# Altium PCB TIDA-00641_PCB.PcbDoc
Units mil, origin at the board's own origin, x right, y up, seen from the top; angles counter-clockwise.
Board outline 1800 x 1950 mil, 2 copper layers (Top Layer, Bottom Layer), stack 62 mil thick; 47 components, 47 nets, 167 pads, 110 vias.
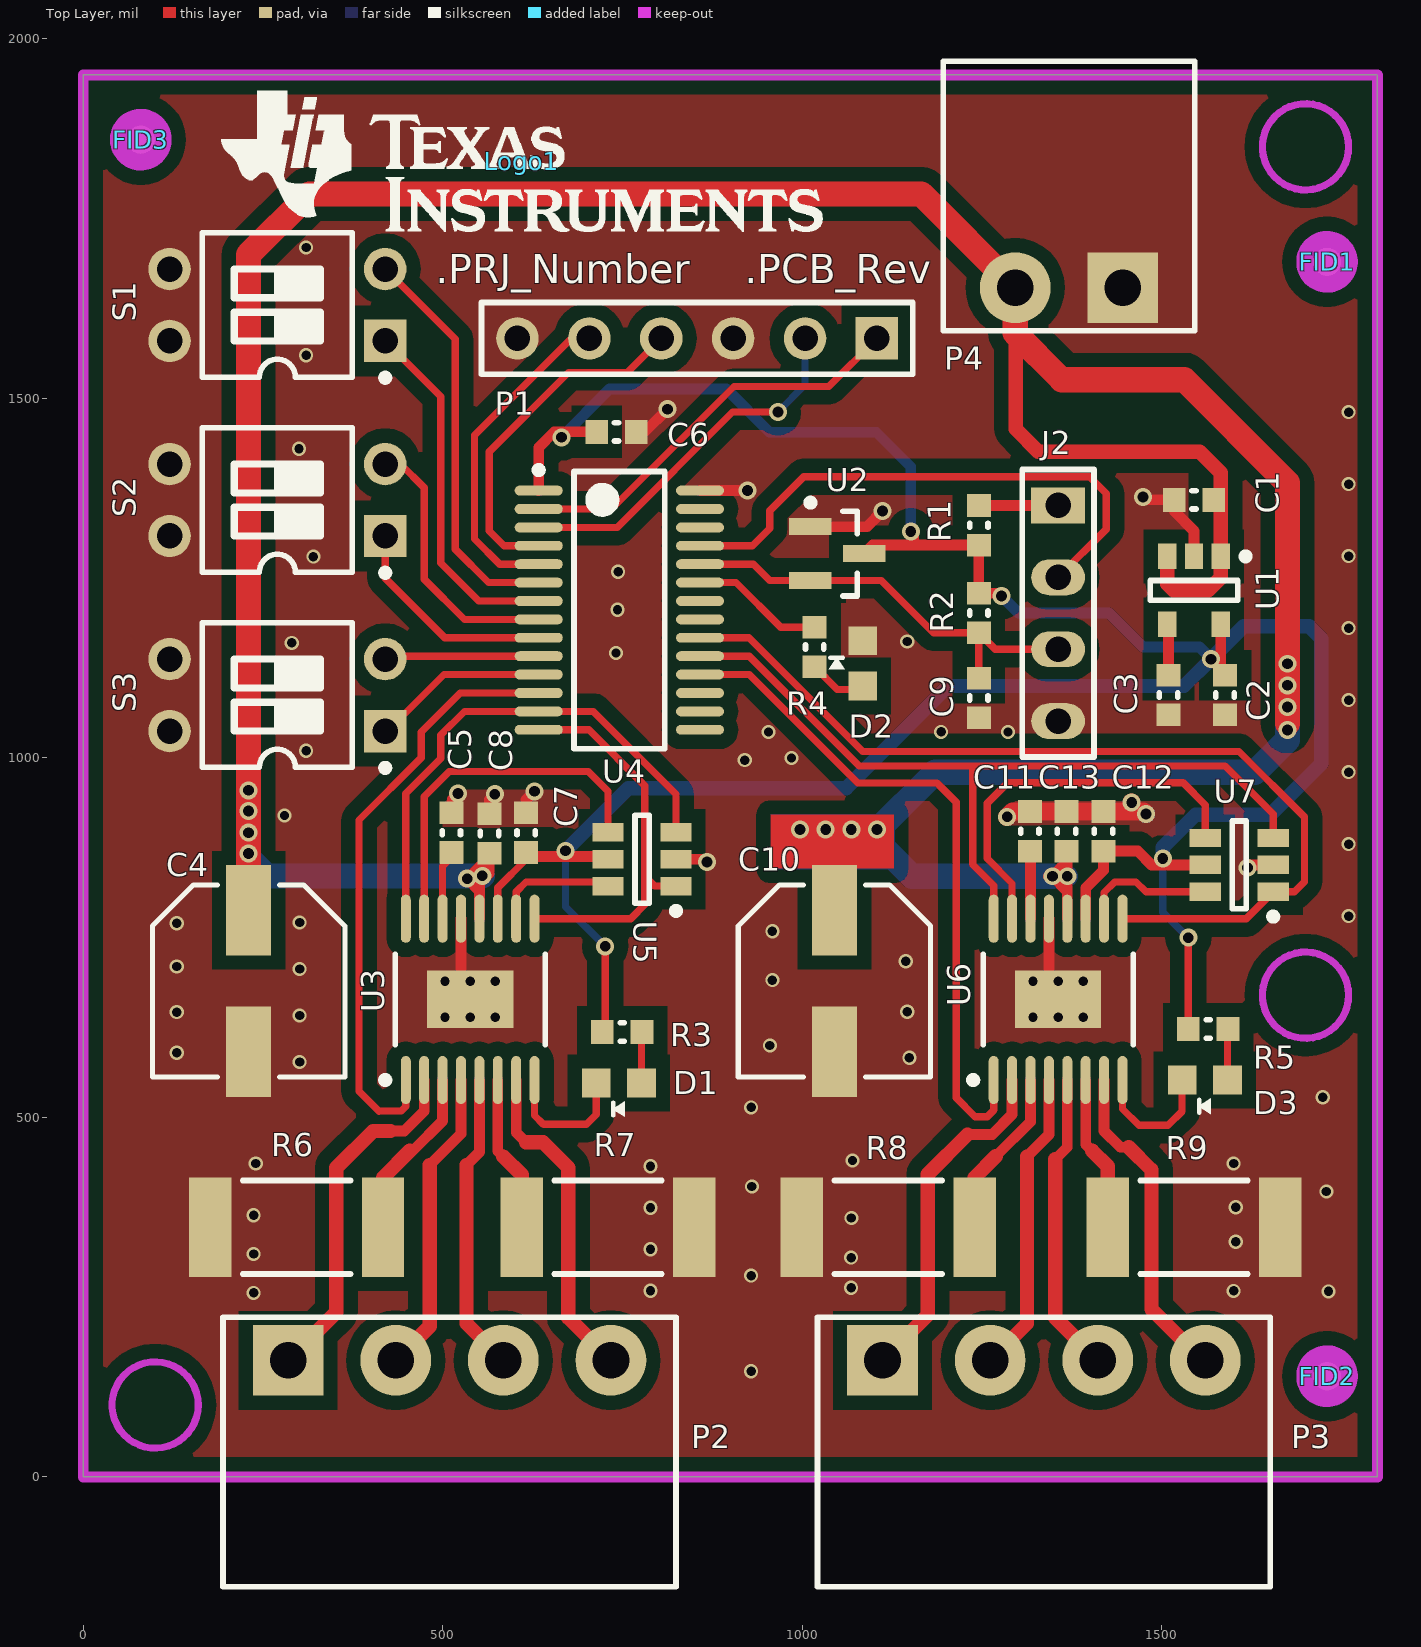
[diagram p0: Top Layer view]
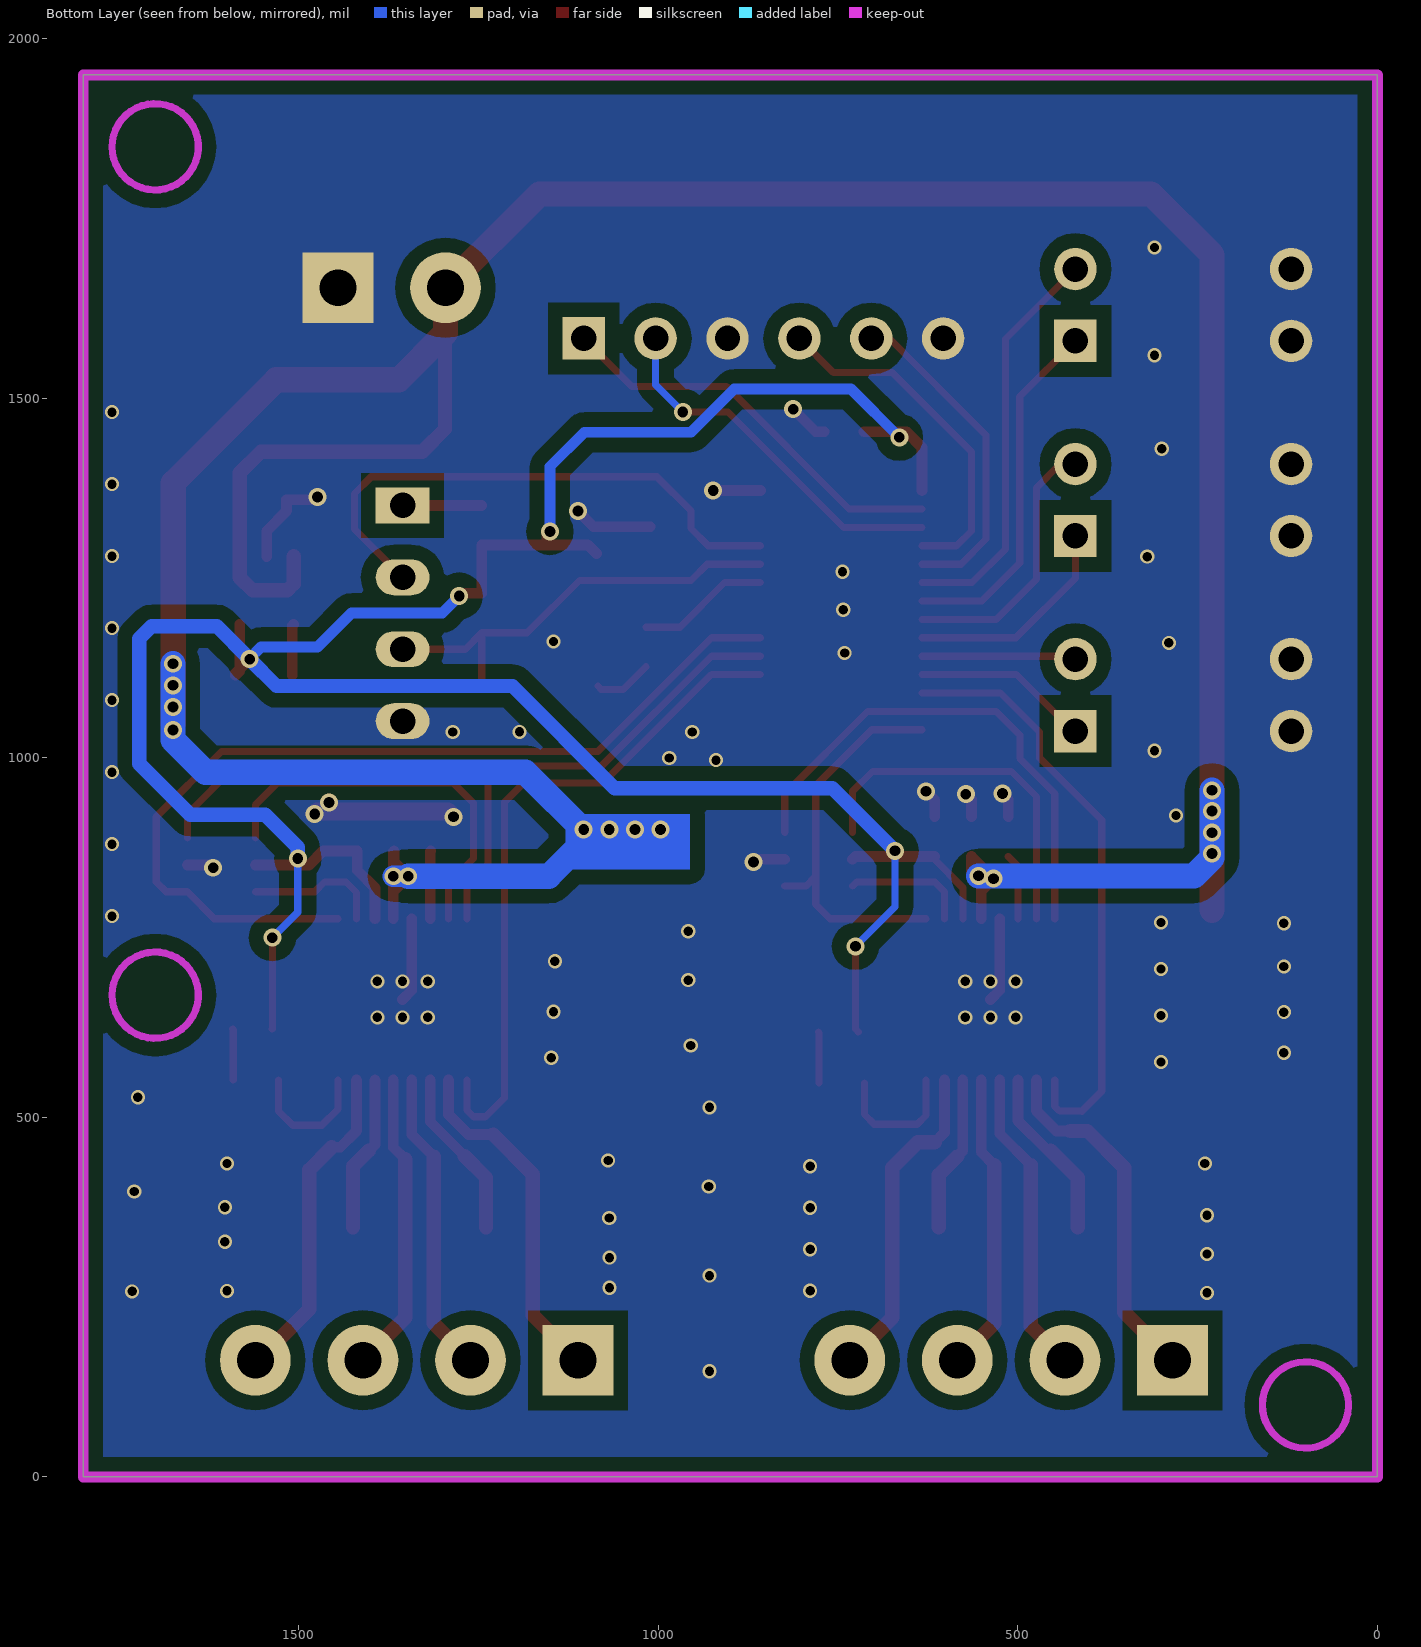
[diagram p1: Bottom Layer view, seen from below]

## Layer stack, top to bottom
Top Solder: solder mask 0.4, Solder Resist, Dk 3.5
Top Layer: signal copper 1.4
Dielectric1: core 59.2, FR-4, Dk 4.8
Bottom Layer: signal copper 1.4
Bottom Solder: solder mask 0.4, Solder Resist, Dk 3.5

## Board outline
0,0 1800,0 1800,1950 0,1950

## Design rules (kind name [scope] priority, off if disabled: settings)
AcuteAngle [All] p1: minimum=4.50000000000000E+0001 checktracksonly=FALSE
AssemblyTestPointUsage [All] p1: valid=2
Clearance Clearance_Keepouts [((IsTrack Or IsArc) And Not InPoly) And IsFree and IsKeepOut vs ((IsTrack Or IsArc) And Not InPoly) And IsFree and IsKeepOut] p1: gap=0
Clearance Clearance_BoardEdge_MountingHoles [OnCopper and InComponentClass('Mounting Holes') vs IsKeepOut] p2: gap=40
Clearance Clearance_BoardEdge_Poly [OnCopper and InPoly vs IsKeepOut] p3: gap=20
Clearance Clearance_BoardEdge [OnCopper and Not InComponentClass('Logo') and not InComponentClass('FiducialMark') and not InRegion(1000,500,4000,800) and Not IsKeepout vs IsKeepOut] p4: gap=20
Clearance Clearance_Poly [InPolygon] p5: gap=20
Clearance [All] p6: gap=8
ComponentClearance ComponentClearance_MountingHoles_FiducialMarks [InComponentClass('Mounting Holes') vs InComponentClass('FiducialMark')] p1 off: gap=50 collisioncheckmode=3 verticalgap=10 showdistances=FALSE
ComponentClearance ComponentClearance_Shunt [InComponentClass('Header') vs InComponentClass('Shunt')] p2 off: gap=0 collisioncheckmode=3 verticalgap=0 showdistances=FALSE
ComponentClearance ComponentClearance_Logo [InComponentClass('Logo')] p3 off: gap=50 collisioncheckmode=3 verticalgap=10 showdistances=FALSE
ComponentClearance ComponentClearance_ScrewToNut [(HasFootprint('NY PMS 440 0025 PH')) vs (HasFootprint('Keystone_1902C'))] p4 off: gap=5 collisioncheckmode=3 verticalgap=10 showdistances=FALSE
ComponentClearance ComponentClearance_MountingHoles [InComponentClass('Mounting Holes')] p5 off: gap=250 collisioncheckmode=3 verticalgap=100000 showdistances=FALSE
ComponentClearance ComponentClearance_SmallPassives [HasFootprint('0201*') or HasFootprint('0402*') or HasFootprint('0508') or HasFootprint('0603*') or HasFootprint('0612') or HasFootprint('0805*') or HasFootprint('0815*') or HasFootprint('0830*') or HasFootprint('1206*') or HasFootprint('1210*') or HasFootprint('1808*') or HasFootprint('1812*') or HasFootprint('1825*') or HasFootprint('2010*') or HasFootprint('2220*') or HasFootprint('2225*') or HasFootprint('2512*') or HasFootprint('2728*') or HasFootprint('3518*') vs HasFootprint('0201*') or HasFootprint('0402*') or HasFootprint('0508') or HasFootprint('0603*') or HasFootprint('0612') or HasFootprint('0805*') or HasFootprint('0815*') or HasFootprint('0830*') or HasFootprint('1206*') or HasFootprint('1210*') or HasFootprint('1808*') or HasFootprint('1812*') or HasFootprint('1825*') or HasFootprint('2010*') or HasFootprint('2220*') or HasFootprint('2225*') or HasFootprint('2512*') or HasFootprint('2728*') or HasFootprint('3518*')] p6 off: gap=20 collisioncheckmode=3 verticalgap=10 showdistances=FALSE
ComponentClearance ComponentClearance_THtoSMT [IsThruComponent vs IsSMTComponent] p7 off: gap=100 collisioncheckmode=3 verticalgap=30 showdistances=FALSE
ComponentClearance ComponentClearance_THtoTH [IsThruComponent vs IsThruComponent] p8 off: gap=118.11 collisioncheckmode=3 verticalgap=30 showdistances=FALSE
ComponentClearance [All] p9 off: gap=0 collisioncheckmode=3 verticalgap=10 showdistances=FALSE
DiffPairsRouting [All] p1: maxlimit=100 minlimit=10 mostfreqgap=10 toplayer_minwidth=15 toplayer_maxwidth=15 toplayer_prefwidth=15 bottomlayer_minwidth=15 bottomlayer_maxwidth=15 bottomlayer_prefwidth=15 maxuncoupledlength=1000
FabricationTestPointUsage TestPointUsage [All] p1: valid=2 allowmultiple=FALSE
FabricationTestpoint Testpoint [All] p1: side=3 testpointundercomponent=TRUE minsize=40 maxsize=100 preferedsize=60 minholesize=0 maxholesize=40 preferedholesize=32 testpointgrid=1 allowsidetop=TRUE allowsidebottom=TRUE usegrid=TRUE gridtolerance=0.01
FanoutControl Fanout_LCC [IsLCC] p1: bgadir=Out bgaviamode=Centered fanoutstyle=Auto fanoutdirection=Alternating viagrid=1 // Fanout_LCC (Default Rule)
FanoutControl Fanout_BGA [IsBGA] p2: bgadir=Out bgaviamode=Centered fanoutstyle=Auto fanoutdirection=Alternating viagrid=1 // Fanout_BGA (Default Rule)
FanoutControl Fanout_Default [All] p4: bgadir=Out bgaviamode=Centered fanoutstyle=Auto fanoutdirection=Alternating viagrid=1 // Fanout_Default (Default Rule)
FanoutControl Fanout_Small [(CompPinCount < 5)] p5: bgadir=Out bgaviamode=Centered fanoutstyle=Auto fanoutdirection=OutThenIn viagrid=1 // Fanout_Small (Default Rule)
HoleSize [All] p1: absolutevalues=TRUE maxlimit=251 minlimit=8 maxpercent=80.000 minpercent=20.000
MinimumAnnularRing MinimumAnnularRing_ThermalPadVias [IsVia and InAnyComponent] p1: minimumring=5.91
MinimumAnnularRing [All] p2: minimumring=9
PlaneConnect [All] p1: planeconnectstyle=Relief reliefexpansion=10 reliefentries=4 reliefconductorwidth=10 reliefairgap=10
PolygonConnect [All] p1: connectstyle=Direct reliefconductorwidth=10 reliefentries=4 polygonreliefangle="90 Angle" airgapwidth=10
RoutingVias ThermalPadVias [IsVia and InAnyComponent] p1 off: holewidth=7.87 width=19.68 viastyle="Through Hole" minholewidth=7.87 minwidth=19.68 maxholewidth=12.99 maxwidth=23.62
RoutingVias [All] p2 off: holewidth=16 width=34 viastyle="Through Hole" minholewidth=7.87 minwidth=26 maxholewidth=40 maxwidth=65
SilkToBoardRegionClearance [Not ((IsComment or IsDesignator) And (Hide <> 'False')) and not InRegion(1000,500,4000,800)] p1:
SilkToSilkClearance SilkToSilkClearance_Pb-FreeLogo [(HasFootprint('Pb-Free_Overlay_Medium') OR HasFootprint('Pb-Free_Overlay_Small')) vs (HasFootprint('Pb-Free_Overlay_Medium') OR HasFootprint('Pb-Free_Overlay_Small'))] p1: silktosilkclearance=0
SilkToSilkClearance [All] p2: silktosilkclearance=4
SolderMaskExpansion [All] p1: expansion=1.97
UnpouredPolygon [All] p1: allowunpoured=FALSE
Width [All] p1: maxlimit=100 minlimit=6 preferedwidth=10 checkconnectedcopper=TRUE
16 further rules are at their usual default settings.

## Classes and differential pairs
component class Logo: Logo1
component class TIDA-00641_TID_Hardware: FID1 FID2 FID3 Logo1 ZZ2 ZZ3 ZZ4
component class FiducialMark: FID1 FID2 FID3
component class AssemblyNote: ZZ2 ZZ3 ZZ4
component class Header: J2
component class TIDA-00641_BlankSheet: C1 C2 C3 C4 C5 C6 C7 C8 C9 C10 C11 C12 C13 D1 D2 D3 J2 P1 P2 P3 P4 R1 R2 R3 R4 R5 R6 R7 R8 R9 S1 S2 S3 U1 U2 U3 U4 U5 U6 U7

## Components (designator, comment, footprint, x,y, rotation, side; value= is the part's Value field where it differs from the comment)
C1 "C0603C105K4PACTU" 0603L 1544.88,1359.06 r180 top
C2 "C0603C225K8PACTU" 0603L 1588.19,1087.4 r90 top
C3 "C0603C103J5RACTU" 0603L 1509.45,1087.4 r270 top
C4 "EEE-FK1E470P" SM_RADIAL_D 229.92,689.76 r270 top
C5 "C0603C225M8PACTU" 0603L 512,896 r90 top
C6 "C0603C104K4RACTU" 0603L 741.73,1453.54 r180 top
C7 "06033C104KAT2A" 0603L 616,896 r270 top
C8 "06033C104KAT2A" 0603L 565,895 r270 top
C9 "C0603C102K5RACTU" 0603L 1245.67,1083.46 r90 top
C10 "EEE-FK1E470P" SM_RADIAL_D 1044.88,689.76 r270 top
C11 "C0603C225K8PACTU" 0603L 1316.54,897.93 r90 top
C12 "06033C104KAT2A" 0603L 1418.9,897.93 r270 top
C13 "06033C104KAT2A" 0603L 1367.72,897.93 r270 top
D1 "LTST-C190KRKT" LED603RED 745.67,548.03 r0 top
D2 "LTST-C190GKT" LED603GRN 1084.25,1130.71 r270 top
D3 "LTST-C190KRKT" LED603RED 1560.63,551.97 r0 top
FID1 "Fiducial" Fiducial10-20 1730,1690 r0 top
FID2 "Fiducial" Fiducial10-20 1730,140 r0 top
FID3 "Fiducial" Fiducial10-20 80,1860 r0 top
J2 "TSW-104-07-G-S" HDR1X4 1355.91,1351.18 r270 top
Logo1 "Texas Instruments" TI_Stacked_Overlay_Small 610,1830 r0 top
P1 "Header 6" HDR1X6 1103.94,1583.46 r180 top
P2 "Header 4" J4-3.81 509.45,162.2 r0 top
P3 "Header 4" J4-3.81 1336.22,162.2 r0 top
P4 "Header 2" j2-3.81 1371,1654 r180 top
R1 "ERJ-3GEY0R00V" 0603L 1245.67,1323.62 r90 top
R2 "CRCW060347K0JNEA" 0603L 1245.67,1201.57 r270 top
R3 "RC0603FR-07390RL" 0603L 749.61,618.9 r180 top
R4 "RC0603FR-07390RL" 0603L 1017.32,1154.33 r90 top
R5 "RC0603FR-07390RL" 0603L 1564.57,622.83 r180 top
R6 "CSRN2512FKR250" 2512M 296.85,347.24 r0 top
R7 "CSRN2512FKR250" 2512M 729.92,347.24 r180 top
R8 "CSRN2512FKR250" 2512M 1119.68,347.24 r0 top
R9 "CSRN2512FKR250" 2512M 1544.88,347.24 r180 top
S1 "SW DIP-2" DIP-4 270,1630 r180 top
S2 "SW DIP-2" DIP-4 270,1358.7 r180 top
S3 "SW DIP-2" DIP-4 270,1087.4 r180 top
U1 "LP2985-33DBVT" MF05A_L 1544.88,1233.07 r270 top
U2 "TLV803S" SOT-23 1048.82,1284.25 r0 top
U3 "DRV8848" PW0016S 538.19,664.17 r90 top
U4 "MSP430G2553IPW28" PW0028A_N 745.67,1205.51 r0 top
U5 "SN74LVC2G14" DBV0006A_N 777.17,859.06 r180 top
U6 "DRV8848" PW0016S 1355.91,664.17 r90 top
U7 "SN74LVC2G14" DBV0006A_N 1607.87,851.18 r180 top
ZZ2 "These assemblies are ESD sensitive, ESD precautions shall be observed." AssemblyNote 185,3829.11 r0 top
ZZ3 "These assemblies must be clean and free from flux and all contaminants. Use of no clean flux is not acceptable." AssemblyNote 185,3740.56 r0 top
ZZ4 "These assemblies must comply with workmanship standards IPC-A-610 Class 2, unless otherwise specified." AssemblyNote 185,3652 r0 top

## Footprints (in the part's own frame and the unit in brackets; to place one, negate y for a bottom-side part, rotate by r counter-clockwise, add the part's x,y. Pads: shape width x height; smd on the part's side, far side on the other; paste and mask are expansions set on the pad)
0603L [mm] "0603 from SM-752 data"
  rect 0.8x0.85 smd: 1(-0.7,0) 2(0.7,0)
  silkscreen extent -0.07,-0.33 0.07,0.33, body extent -0.87,-0.47 0.87,0.47, height 0.85
2512M [mm] "Chip Resistor, Body 6.3x3.2mm, IPC Low Density"
  rect 1.5x3.5 smd: 1(-3.05,0) 2(3.05,0)
  silkscreen extent -1.9,-1.65 1.9,1.65, body extent -3.22,-1.67 3.22,1.67, height 0.71
AssemblyNote [mil] "Assembly Note"
DBV0006A_N [mm] "SOT23, 6-Leads, Body 2.9x1.6mm, Pitch 0.95mm, Lead Span 2.8mm, IPC Medium Density"
  rect 1.1x0.65 smd: 1(-1.2,0.95) 2(-1.2,0) 3(-1.2,-0.95) 4(1.2,-0.95) 5(1.2,0) 6(1.2,0.95)
  silkscreen extent -1.33,-1.55 0.25,1.95, body extent -0.87,-1.52 0.87,1.53, height 1.45
DIP-4 [mm] "DIP; 4 Leads; Row Spacing 7.62 mm; Pitch 2.54 mm"
  rect 1.5x1.5 hole 0.9: 1(-3.81,1.27)
  round 1.5 hole 0.9: 2(-3.81,-1.27) 3(3.81,-1.27) 4(3.81,1.27)
  silkscreen extent -3.94,-2.55 2.65,2.69, body extent -3.15,-2.5 3.15,2.5, height 5.6
Fiducial10-20 [mm]
  round 1 smd mask+0.5: 1(0,0)
  Top Layer keep-out circle w1.178: c0,0 r0.5
HDR1X4 [mm] "Connector; Header; 4 Position"
  rect 1.27x1.9 hole 0.9: 1(0,0)
  oval 1.27x1.9 hole 0.9: 2(2.54,0) 3(5.08,0) 4(7.62,0)
  silkscreen extent -1.27,-1.27 8.89,1.27
HDR1X6 [mm] "Connector; Header; 6 Position"
  rect 1.5x1.5 hole 0.9: 1(0,0)
  round 1.5 hole 0.9: 2(2.54,0) 3(5.08,0) 4(7.62,0) 5(10.16,0) 6(12.7,0)
  silkscreen extent -1.27,-1.27 13.97,1.27
j2-3.81 [mm] "Connector; Header; 4 Position"
  rect 2.5x2.5 hole 1.3: 1(-1.9,0)
  round 2.5 hole 1.3: 2(1.9,0)
  silkscreen extent -4.44,-8 4.45,1.52
J4-3.81 [mm] "Connector; Header; 4 Position"
  rect 2.5x2.5 hole 1.3: 1(-5.7,0)
  round 2.5 hole 1.3: 2(-1.9,0) 3(1.9,0) 4(5.7,0)
  silkscreen extent -8,-8 8,1.52
LED603GRN [mil]
  rect 40x40 smd: 1(-32.2,-0.1) 2(30.8,-0.1)
  silkscreen extent -10,-47 7,-25, body extent -26,-29 26,29, height 43
LED603RED [mil]
  rect 40x40 smd: 1(-32.2,-0.1) 2(30.8,-0.1)
  silkscreen extent -10,-47 7,-25, body extent -26,-29 26,29, height 43
MF05A_L [mm] "SOT23, 5-Leads, Body 2.9x1.6mm, Pitch 0.95mm, Lead Span 2.8mm, IPC High Density"
  rect 0.9x0.65 smd: 1(-1.2,0.95) 2(-1.2,0) 3(-1.2,-0.95) 4(1.2,-0.95) 5(1.2,0.95)
  silkscreen extent -1.32,-1.55 0.35,1.95, body extent -0.9,-1.55 0.9,1.55, height 1.19
PW0016S [mm]
  oval 1.7x0.35 smd: 1(-2.85,2.275) 2(-2.85,1.625) 3(-2.85,0.975) 4(-2.85,0.325) 5(-2.85,-0.325) 6(-2.85,-0.975) 7(-2.85,-1.625) 8(-2.85,-2.275) 9(2.85,-2.275) 10(2.85,-1.625) 11(2.85,-0.975) 12(2.85,-0.325) 13(2.85,0.325) 14(2.85,0.975) 15(2.85,1.625) 16(2.85,2.275)
  rect 2.032x3.048 smd: 17(0,0)
  silkscreen extent -2.97,-2.65 1.6,3.12, body extent -3.21,-2.5 3.21,2.5, height 0.99
PW0028A_N [mm] "TSOP, 28-Leads, Body 9.7x4.4mm, Pitch 0.65mm, IPC Medium Density"
  oval 1.7x0.35 smd: 1(-2.85,4.225) 2(-2.85,3.575) 3(-2.85,2.925) 4(-2.85,2.275) 5(-2.85,1.625) 6(-2.85,0.975) 7(-2.85,0.325) 8(-2.85,-0.325) 9(-2.85,-0.975) 10(-2.85,-1.625) 11(-2.85,-2.275) 12(-2.85,-2.925) 13(-2.85,-3.575) 14(-2.85,-4.225) 15(2.85,-4.225) 16(2.85,-3.575) 17(2.85,-2.925) 18(2.85,-2.275) 19(2.85,-1.625) 20(2.85,-0.975) 21(2.85,-0.325) 22(2.85,0.325) 23(2.85,0.975) 24(2.85,1.625) 25(2.85,2.275) 26(2.85,2.925) 27(2.85,3.575) 28(2.85,4.225)
  silkscreen extent -2.97,-4.9 1.6,5.07, body extent -2.25,-4.9 2.25,4.9, height 1.2
SM_RADIAL_D [mm] "6.3 x 5.8mm:  Panasonic D"
  rect 3.2x1.6 smd: 1(-2.5,0) 2(2.5,0)
  silkscreen extent -3.4,-3.4 3.4,3.4, body extent -3.41,-3.41 3.41,3.41, height 6.1
SOT-23 [mm] "SOT23, 3-Leads, Body 2.9x1.3mm, Pitch 0.95mm, Lead Span 2.5mm, IPC Medium Density"
  rect 1.5x0.6 smd: 1(-0.95,0.95) 2(-0.95,-0.95) 3(0.95,0)
  silkscreen extent -1.07,-1.5 0.7,1.92, body extent -1.16,-1.45 1.21,1.45, height 1
TI_Stacked_Overlay_Small [mil]
  silkscreen extent -418,-98 418,98

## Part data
C1: "CAP, CERM, 1uF, 16V, +/-10%, X5R, 0603"
C2 C11: "CAP, CERM, 2.2uF, 10V, +/-10%, X5R, 0603"
C3: "CAP, CERM, 0.01uF, 50V, +/-5%, X7R, 0603"
C4 C10: "CAP, AL, 47uF, 25V, +/-20%, 0.36 ohm, SMD"
C5: "CAP, CERM, 2.2uF, 10V, +/-20%, X5R, 0603"
C6: "CAP, CERM, 0.1uF, 16V, +/-10%, X7R, 0603"
C7 C8 C12 C13: "CAP, CERM, 0.1uF, 25V, +/-10%, X7R, 0603"
C9: "CAP, CERM, 1000pF, 50V, +/-10%, X7R, 0603"
D1 D3: library part D_LED_603_GRN, "LED SUPER RED CLEAR 0603 SMD"
D2: library part D_LED_603_GRN, "Diode, LED, Green, 2.1-V, 20-mA, 6-mcd"
FID1 FID2 FID3: "Fiducial mark.  There is nothing to buy or mount."
J2: "Header, TH, 100mil, 4x1, Gold plated, 230 mil above insulator"
Logo1: library part TI_Logo, "Texas Instrument Corporate Signature"
P1: "Header, 6-Pin"
P2 P3: "Header, 4-Pin"
P4: "Header, 2-Pin"
R1: "RES, 0 ohm, 5%, 0.1W, 0603"
R2: "RES, 47k ohm, 5%, 0.1W, 0603"
R3 R4 R5: "RES, 390 ohm, 1%, 0.1W, 0603"
R6 R7 R8 R9: "RES, 0.25 ohm, 1%, 2W, 2512"
S1 S2 S3: "SWITCH TIN CONT 2 SEC 50V"
U1: library part LP2985IM5-3.3, "Micropower 150 mA Low-Noise Ultra Low-Dropout Regulator, 5-pin SOT-23"
U2: library part TLV803DBZ, "IC VOLT SUPERVISR 2.93V SOT23-3"
U3 U6: library part DRV8848PWP, "IC MOTOR DRIVER PAR 16HTSSOP"
U4: "IC MCU 16BIT 16KB FLASH 28TSSOP"
U5 U7: "Dual Schmitt-Trigger Inverter"
ZZ2 ZZ3 ZZ4: library part AssemblyNote

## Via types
v1: diameter 19.68, hole 13, Top Layer to Bottom Layer, 73 vias
v2: diameter 25, hole 15, Top Layer to Bottom Layer, 37 vias

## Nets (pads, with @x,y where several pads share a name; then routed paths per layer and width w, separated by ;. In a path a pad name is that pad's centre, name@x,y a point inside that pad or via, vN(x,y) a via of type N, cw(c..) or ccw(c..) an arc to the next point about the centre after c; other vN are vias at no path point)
DIR1: P1.2 U4.3 | length 517.1
  Top Layer w10: U4.3 742.72,1320.67 903.15,1481.1 v2(966.14,1481.1)
  Bottom Layer w10: v2(966.14,1481.1) 1003.94,1518.9 P1.2
DIR2: P1.5 U4.5 | length 463.6
  Top Layer w10: U4.5 579.33,1269.49 544.21,1304.61 544.21,1448.94 678.74,1583.46 P1.5
DRV1-AIN1-TA11: U3.16 U4.13 U5.3 | length 717.3
  Top Layer w10: U3.16 448.62,950.46 497.28,999.11 497.28,1031.92 530.12,1064.76 U4.13 709.25,1064.76 824.41,949.61 U5.3
DRV1-AIN2: U3.15 U5.4 | length 508.5
  Top Layer w10: U3.15 474.21,946.23 509.09,981.1 702.36,981.1 729.92,953.54 U5.4
DRV1-AOUT1: P2.1 U3.2 | length 493.5
  Top Layer w15: 427.36,481.1 446.46,481.1 474.21,508.86 U3.2
  Top Layer w20: P2.1 351.97,229.13 351.97,429.92 403.15,481.1 427.36,481.1
DRV1-AOUT2: P2.2 U3.4 | length 427.4
  Top Layer w15: 481.89,433.86 525.39,477.36 U3.4
  Top Layer w20: P2.2 481.89,209.45 481.89,433.86
DRV1-BIN1-TA12: U3.9 U4.14 U5.1 | length 555.7
  Top Layer w10: U3.9 761.42,776.38 781.1,796.06 781.1,835.43 ; U4.14 703.35,1039.17 781.1,961.42 781.1,835.43 ; U5.1 794.88,821.65 781.1,835.43
DRV1-BIN2: U3.10 U5.6 | length 173.4
  Top Layer w10: U3.10 602.17,813.98 615.75,827.56 724.02,827.56 U5.6
DRV1-BOUT1: P2.4 U3.7 | length 458.2
  Top Layer w15: U3.7 602.17,478.94 615.75,465.35
  Top Layer w20: 615.75,465.35 639.37,465.35 674.8,429.92 674.8,221.26 P2.4
DRV1-BOUT2: P2.3 U3.5 | length 418.4
  Top Layer w15: 533.07,433.86 550.98,451.77 U3.5
  Top Layer w20: 533.07,433.86 533.07,213.39 P2.3
DRV1-NSLEEP: U3.1 U4.12 | length 837.7
  Top Layer w10: U3.1 448.62,515.09 442.36,508.82 411.38,508.82 411.22,508.66 383.46,536.42 383.46,913.58 470.08,1000.2 470.08,1036.22 524.21,1090.35 U4.12
DRV2-AIN1-TA01: U4.19 U6.16 U7.3 | length 1146.5
  Top Layer w10: U4.19 926.24,1141.54 1078.8,988.98 1588.19,988.98 1655.12,922.05 U7.3 ; 1237.8,988.98 1237.26,988.44 1237.26,851.72 1266.34,822.64 U6.16
DRV2-AIN2: U6.15 U7.4 | length 548.8
  Top Layer w10: U6.15 1291.93,825.33 1257.26,860 1257.26,936.85 1285.76,965.35 1529.98,965.35 1560.63,934.71 U7.4
DRV2-AOUT1: P3.1 U6.2 | length 484.5
  Top Layer w15: 1229.92,476.18 1264.25,476.18 1291.93,503.86 U6.2
  Top Layer w20: P3.1 1174.8,225.2 1174.8,421.06 1229.92,476.18
DRV2-AOUT2: P3.2 U6.4 | length 423.6
  Top Layer w15: 1312.6,445.67 1343.11,476.18 U6.4
  Top Layer w20: P3.2 1312.6,213.39 1312.6,445.67
DRV2-BIN1-TA02: U4.20 U6.9 U7.1 | length 1308.4
  Top Layer w10: U4.20 926.1,1167.13 1084.25,1008.98 1607.56,1008.98 1698.43,918.11 1698.43,827.56 1684.65,813.78 U7.1 1617.72,776.38 U6.9
DRV2-BIN2: U6.10 U7.6 | length 189
  Top Layer w10: U6.10 1419.88,812.8 1434.65,827.56 1464.37,827.56 1478.15,813.78 U7.6
DRV2-BOUT1: P3.4 U6.7 | length 457.3
  Top Layer w15: U6.7 1419.88,481.1 1442.52,458.46 1454.33,458.46
  Top Layer w20: 1454.33,458.46 1485.83,426.97 1485.83,233.07 1556.69,162.2 P3.4
DRV2-BOUT2: P3.3 U6.5 | length 421.2
  Top Layer w15: 1351.97,441.73 1368.7,458.46 U6.5
  Top Layer w20: 1351.97,441.73 1351.97,221.26 P3.3
DRV2-NSLEEP: U4.18 U6.1 | length 949.6
  Top Layer w10: U4.18 926.37,1115.94 1077,965.32 1187.14,965.32 1214.17,938.28 1214.17,828.14 1214.17,527.28 1240.45,501.01 1257.26,501.01 1266.34,510.09 U6.1
GND: C1.2 C2.1 C3.2 C4.2 C5.2 C6.1 C7.1 C8.1 C9.1 C10.2 C11.2 C12.1 C13.1 D2.1 J2.4 P1.3 P1.6 P4.1 R6.1 R7.1 R8.1 R9.1 S1.3 S1.4 S2.3 S2.4 S3.3 S3.4 U1.2 U2.1 U3.13 U3.17 U4.28 U5.2 U6.13 U6.17 U7.2 | length 1006.1
  Top Layer w15: C5.2@513.39,918.11 513.39,942.58 v2(521.26,950.46) ; U3.13 525.39,676.97 U3.17 ; C8.1@564.57,918.11 564.57,941.73 v2(572.44,949.61) ; C7.1@615.75,918.11 615.75,941.54 v2(627.76,953.54) ; C6.1 781.1,1453.54 v2(812.6,1485.04) ; U5.2 863.78,859.06 v2(867.72,855.12) ; U4.28 v2(923.82,1371.85) ; U2.1 1090.16,1321.65 v2(1111.81,1343.31) ; U6.13 1343.11,676.97 U6.17 ; v2(1474.02,1362.99) 1477.95,1359.06 C1.2 1517.32,1343.31 1544.88,1315.75 U1.2 ; v2(1619.27,847.24) 1623.21,851.18 U7.2
  Top Layer w25: v2(1285.04,918.11) 1292.42,925.49 C11.2 v2@1458.27,925.49 ; v2(1458.27,937.85) v2@1458.27,925.49 ; v2(1478.15,922.05) 1474.71,925.49 v2@1458.27,925.49
  Bottom Layer w15: v2(923.82,1371.85) v2@925,1371.85
  other v1: 929,147 237,256 1732,258 789,259 1600,258.66 1068,263 929,280 1068,305 237,310 789,316.67 1603,327 1068.33,360 237,364 789,374.33 1603,375 1729,397 930,404 789,432 240,435.83 1600,435.83 1070,440 929,514 1724,528 301,577 1149,583 130,590 955.07,599.95 503.19,639.17 538.19,639.17 573.19,639.17 1320.91,639.17 1355.91,639.17 1390.91,639.17 301,641.67 130,646.46 1146,647 503.19,689.17 538.19,689.17 573.19,689.17 1320.91,689.17 1355.91,689.17 1390.91,689.17 958.44,691 301,706.33 130,710 1144,717.2 958.44,759 130,770 301,771 1760,780 1760,880.14 280,920 1760,980.29 920,997 985,1000 310,1010 953,1036 1193.16,1036.22 1286.12,1036 1760,1080.43 741,1146 290,1160 1146,1162 1760,1180.57 743,1206 744,1259 320,1280 1760,1280.71 1760,1380.86 300,1430 1760,1481 310,1560 310,1710
NetC3_1: C3.1 U1.4 | length 71.7
  Top Layer w15: U1.4 1509.45,1183.86 C3.1
NetC5_1: C5.1 U3.14 | length 92.2
  Top Layer w10: U3.14 499.8,849.41 C5.1@513.39,862.99
NetC11_1: C11.1 U6.14 | length 94.4
  Top Layer w15: C11.1 1317.52,869.39 U6.14
NetD1_1: D1.1 U3.8 | length 189.8
  Top Layer w10: U3.8 627.76,502.56 639.96,490.35 699.8,490.35 713.47,504.02 D1.1
NetD1_2: D1.2 R3.1 | length 71.3
  Top Layer w10: D1.2 776.47,618.2 R3.1
NetD2_2: D2.2 R4.1 | length 81.8
  Top Layer w10: R4.1 1048.82,1095.28 1079.52,1095.28 D2.2
NetD3_1: D3.1 U6.8 | length 183.9
  Top Layer w10: U6.8 1445.47,511.81 1468.31,488.98 1508.74,488.98 1528.43,508.66 D3.1
NetD3_2: D3.2 R5.1 | length 71.3
  Top Layer w10: D3.2 1591.43,622.14 R5.1
NetR6_2: R6.2 U3.3 | length 237.4
  Top Layer w15: 458.27,453.54 499.8,495.08 U3.3
  Top Layer w20: R6.2 416.93,416.14 454.33,453.54
NetR7_2: R7.2 U3.6 | length 218.5
  Top Layer w15: U3.6 576.57,453.35 584.25,445.67
  Top Layer w20: 584.25,445.67 609.84,420.08 R7.2
NetR8_2: R8.2 U6.3 | length 236.9
  Top Layer w15: 1269.29,445.87 1317.52,494.09 U6.3
  Top Layer w20: R8.2 1239.76,416.34 1269.29,445.87
NetR9_2: R9.2 U6.6 | length 217.4
  Top Layer w15: U6.6 1394.29,462.4 1403.15,453.54
  Top Layer w20: 1403.15,453.54 1424.8,431.89 R9.2
P1.4: S1.2 U4.6 | length 565.3
  Top Layer w10: S1.2 517.32,1582.68 517.32,1290.35 563.78,1243.9 U4.6
P1.5: S1.1 U4.7 | length 498.9
  Top Layer w10: S1.1 497.32,1502.68 497.32,1271.18 550.2,1218.31 U4.7
P2.0: S3.2 U4.10 | length 211.9
  Top Layer w10: S3.2@423.23,1137.4 427.36,1141.54 U4.10
P2.1: S3.1 U4.11 | length 242.8
  Top Layer w10: S3.1@423.23,1037.4 501.77,1115.94 U4.11
P3.0: S2.1 U4.9 | length 306.5
  Top Layer w10: S2.1 420,1250 502.87,1167.13 U4.9
P3.1: S2.2 U4.8 | length 377.4
  Top Layer w10: S2.2 441.3,1408.7 474.21,1375.79 474.21,1248.62 530.12,1192.72 U4.8
SBWTCK: J2.2 U4.25 | length 773.2
  Top Layer w10: U4.25 930.71,1295.08 954.72,1319.09 954.72,1343.7 1002.2,1391.18 1399.52,1391.18 1422.83,1367.87 1422.83,1318.11 J2.2
SBWTDIO: C9.2 J2.3 R2.2 U2.2 U4.24 | length 610
  Top Layer w10: U4.24 932.09,1269.49 954.72,1246.85 U2.2 1109.84,1246.85 1182.68,1174.02 R2.2 ; C9.2 R2.2 ; J2.3 1268.5,1151.18 R2.2
STATUS: R4.2 U4.23 | length 185.1
  Top Layer w10: U4.23 908.07,1243.9 970.08,1181.89 R4.2
STEP1: P1.1 U4.2 | length 568.7
  Top Layer w10: U4.2 734.84,1346.26 905.12,1516.54 1037.01,1516.54 P1.1
STEP2: P1.4 U4.4 | length 492.3
  Top Layer w10: U4.4 585.24,1295.08 564.57,1315.75 564.57,1425.98 674.8,1536.22 756.69,1536.22 P1.4
V3P3: C2.2 C6.2 C7.2 C12.2 R1.1 R2.1 R3.2 R5.2 U1.5 U2.3 U3.11 U4.1 U5.5 U6.11 U7.5 | length 4192.6
  Top Layer w10: U3.11 576.57,819.56 615.75,858.73 C7.2@615.75,862.99 ; R3.2 726,622.85 v2(726,738) ; R5.2 v2(1537,750)
  Top Layer w15: C7.2@615.75,862.99 v2@670.87,862.99 ; U4.1 633.46,1431.89 655.12,1453.54 C6.2 ; v2(670.87,870.87) v2@670.87,862.99 ; U5.5 725.98,862.99 v2@670.87,862.99 ; U2.3 1098.03,1296.06 1155,1296.06 ; v2(1151,1315) 1155,1311 1155,1296.06 ; v2(1277.17,1225.2) 1281.1,1229.13 R2.1 R1.1 1155,1296.06 ; U6.11 1394.29,819.27 1418.9,843.87 C12.2 1466.64,870.37 1485.83,851.18 v2@1497.64,851.18 ; v2(1501.57,860) 1497.64,856.06 v2@1497.64,851.18 ; U7.5 v2@1497.64,851.18 ; v2(1568.5,1137.4) C2.2@1582.28,1123.62 ; U1.5 C2.2@1582.28,1123.62 ; C2.2@1582.28,1123.62 1588.19,1117.72 C2.2 1582.28,1120.87 C2.2@1582.28,1123.62
  Bottom Layer w10: v2(670.87,870.87) 670.87,793.13 v2(726,738) ; v2(1501.57,860) 1501.57,785.43 v2(1537,750)
  Bottom Layer w15: v2(665,1446) 732.04,1513.04 894.61,1513.04 954.54,1453.1 1102.9,1453.1 1151,1405 v2(1151,1315) ; v2(1277.17,1225.2) 1300.79,1201.57 1426.77,1201.57 1474.02,1154.33 1552.76,1154.33 1569.09,1137.99 v2@1572.44,1134.65
  Bottom Layer w20: v2(670.87,870.87) 758,958 1061,958 1203,1100 1531.1,1100 v2(1568.5,1137.4) 1569.09,1137.99 1614.1,1183 1705,1183 1722,1166 1722,992 1651,921 1547,921 1501.57,875.57 v2(1501.57,860)
VCCX: J2.1 R1.2 | length 110.2
  Top Layer w15: R1.2 J2.1
VM: C1.1 C4.1 C8.2 C10.1 C13.2 P4.2 U1.1 U1.3 U3.12 U6.12 | length 5598.7
  Top Layer w15: U3.12 550.98,815.02 ; C8.2@564.57,862.99 C8.2@564.57,862.57 ; v2@1342.52,835.43 v2(1348,835.43) ; U6.12 1368.7,815 ; 550.98,815.02 550.98,825.79 564.57,839.37 C8.2@564.57,862.57 ; 550.98,815.02 v2(534,832) C8.2@564.57,862.57 ; v2(1348,835.43) v2(1368.7,835.43) ; v2(1348,835.43) 1368.43,815 1368.7,815 ; v2(1348,835.43) 1367.72,855.15 C13.2 1368.7,869.39 v2(1368.7,835.43) ; 1368.7,815 v2(1368.7,835.43)
  Top Layer w20: P4.2@1296.85,1642 1296.85,1457.48 1328.35,1425.98 1552.76,1425.98 1582.28,1396.46 U1.1 1582.28,1250.79 1564.57,1233.07 1516.34,1233.07 1507.48,1241.93 U1.3
  Top Layer w35: C4.1 229.92,1699.92 314.56,1784.56 1165.63,1784.56 P4.2 1296.2,1590.8 1361,1526 1531.48,1526 1674.8,1382.68 v2@1674.8,1048.03 ; P4.2@1296,1659 P4.2@1296.85,1658.15
  Bottom Layer w30: v2@1026.25,898 v2@1106.25,898 ; v2(1348,835.43) v2(1368.7,835.43)
  Bottom Layer w35: v2(230,955) 230,861 255,836 v2(555,836) ; 1090,898 1152.57,835.43 v2(1348,835.43) ; v2@1099,894 1185,980 1630,980 1675,1025 v2(1675,1131)
  other v2: 230,867 230,896 997,900.5 1032.67,900.5 1068.33,900.5 1104,900.5 230,926 1675,1039 1675,1071 1675,1101
pads on no net: FID1.1 FID2.1 FID3.1 U4.15 U4.16 U4.17 U4.21 U4.22 U4.26 U4.27

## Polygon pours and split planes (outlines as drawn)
GND on Bottom Layer "GND Bottom" (solid, remove dead copper, pour order 4): -2.2,1943.37 1797.8,1943.37 1797.8,-3.63 -2.2,-3.63
GND on Top Layer "GND" (solid, remove dead copper, pour order 6): -2.89,1960.37 -2.89,4.37 1797.11,4.37 1797.11,1960.37

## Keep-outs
Keep-Out Layer:
  circle w10: c1700,670 r60
  circle w10: c100,100 r60
  circle w10: c1700,1850 r60
  lines w15: 0,0 1800,0 1800,1950 0,1950 0,0
  text ".Layer_Name" at 577,-858.49 h60

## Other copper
Top Layer:
  rectangle net VM: 956,846 1128,921
  text ".Layer_Name" at 577,-858.49 h60
Bottom Layer:
  rectangle net VM: 956,845 1129,922
  text ".Layer_Name" at 577,-858.49 h60

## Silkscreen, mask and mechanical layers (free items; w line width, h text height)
Top Overlay:
  text ".PRJ_Number" at 490,1660 h40
  text ".PCB_Rev" at 920,1660 h40
  text ".Layer_Name" at 577,-858.49 h60
Bottom Overlay:
  text ".Layer_Name" at 577,-858.49 h60
Top Paste:
  text ".Layer_Name" at 577,-858.49 h60
Bottom Paste:
  text ".Layer_Name" at 577,-858.49 h60
Top Solder:
  text ".Layer_Name" at 577,-858.49 h60
  text ".Layer_Name" at 577,-858.49 h60
Bottom Solder:
  text ".Layer_Name" at 577,-858.49 h60
Drill Guide:
  text ".Layer_Name" at 577,-858.49 h60
M1 Board Outline:
  the board outline again, w6.69
  text ".Layer_Name" at 577,-858.49 h60
M2 Board Dimensions:
  rectangle: 0,-275 125,-150
  rectangle: 125,-400 500,-275
  lines w7: 0,-275 1000,-275 ; 125,-400 125,-150 ; 250,-400 250,-150 ; 500,-400 500,-150 ; 750,-400 750,-150 ; 0,-400 1000,-400 1000,-150 0,-150 0,-400
  text ".Layer_Name" at 577,-858.49 h60
M3 3D STEP Top:
  text ".Layer_Name" at 577,-858.49 h60
M4 3D STEP Bottom:
  text ".Layer_Name" at 577,-858.49 h60
M5 Assembly Top:
  lines w10: -292,-930.17 6308,-930.17 ; -292,-726.83 6310,-726.83 ; -292,-523.5 -292,-1133.5 3713,-1133.5 6310,-1133.5 6310,-523.5 -291.5,-523.5 -291.5,-1133.5 1284,-1133.5 ; 2173,-1133.5 2173,-523.5 ; 3440,-726.83 3440,-523.5 ; 4280,-726.83 4280,-523.5 ; 4902,-1140 4902,-937.17
  text "COMPONENTS MARKED 'DNP' SHOULD NOT BE POPULATED." at 1153.5,-318.5 h60
  text "ASSEMBLY VARIANT:" at 1153,-434 h60
  text ".VariantName" at 2189,-434 h60
  text "PCB VIEWED FROM TOP SIDE" at -228.5,-655.67 h60
  text "BOARD #:" at 2248,-655.67 h60
  text ".PRJ_Number" at 2793.5,-655.67 h60
  text "REV:" at 3638,-655.67 h60
  text ".PCB_Rev" at 3929.5,-655.67 h60
  text "SVN REV:" at 4476,-655.67 h60
  text ".VersionControl_RevNumber" at 4982,-655.67 h60
  text "TID #:" at 2248,-859 h60
  text ".TID" at 2793.5,-859 h60
  text "PLOT NAME =" at -228.5,-1064.34 h60
  text ".plot_File_Name" at 577,-1064.34 h60
  text "GENERATED    :" at 2250,-1064.34 h60
  text ".Print_Date" at 3119.5,-1064.34 h60
  text ".Print_Time" at 3848.5,-1064.34 h60
  text "TEXAS INSTRUMENTS" at 5113,-1064.34 h60
M6 Assembly Bottom:
  lines w10: -292.5,-727.33 6309.5,-727.33 ; -290.5,-930.67 6309.5,-930.67 ; 1115.5,-1140.5 1115.5,-937.67 ; 1737.5,-727.33 1737.5,-524 ; 2577.5,-727.33 2577.5,-524 ; 3844.5,-1134 3844.5,-524 ; 4733.5,-1134 6309,-1134 6309,-524 -292.5,-524 -292.5,-1134 2304.5,-1134 6309.5,-1134 6309.5,-524
  text "COMPONENTS MARKED 'DNP' SHOULD NOT BE POPULATED." at 6102,-318 h60
  text ".VariantName" at 5058,-434 h60
  text "ASSEMBLY VARIANT:" at 6097,-434 h60
  text ".VersionControl_RevNumber" at 1035.5,-656.17 h60
  text "SVN REV:" at 1541.5,-656.17 h60
  text ".PCB_Rev" at 2088,-656.17 h60
  text "REV:" at 2379.5,-656.17 h60
  text ".PRJ_Number" at 3224,-656.17 h60
  text "BOARD #:" at 3769.5,-656.17 h60
  text "PCB VIEWED FROM BOTTOM SIDE" at 6246,-656.17 h60
  text ".TID" at 3224,-859.5 h60
  text "TID #:" at 3769.5,-859.5 h60
  text "TEXAS INSTRUMENTS" at 904.5,-1064.84 h60
  text ".Print_Time" at 2169,-1064.84 h60
  text ".Print_Date" at 2898,-1064.84 h60
  text "GENERATED    :" at 3767.5,-1064.84 h60
  text ".plot_File_Name" at 5440.5,-1064.84 h60
  text "PLOT NAME =" at 6246,-1064.84 h60
M9 Title Sheet:
  drawing of 57 lines, arcs and shapes, not listed
  text "1" at 739.84,8036.5 h70
  text "2" at 3235.5,8036.5 h70
  text "3" at 5724.84,8036.5 h70
  text "4" at 8231.51,8036.5 h70
  text "5" at 10730.5,8036.5 h70
  text "6" at 13235.5,8036.5 h70
  text "A" at -416.5,6893.5 h70
  text "A" at 14383.5,6893.5 h70
  text "B" at -416.5,4513.5 h70
  text "B" at 14383.5,4513.5 h70
  text "C" at -416.5,2138.5 h70
  text "C" at 14383.5,2138.5 h70
  text "PROJECT TITLE:" at 11343.5,277.5 h45
  text ".PRJ_Title" at 11393.5,144.17 h70
  text "DESIGNED FOR:" at 11343.5,-23.5 h45
  text ".PRJ_Customer" at 11393.5,-163.5 h70
  text "D" at -416.5,-231.5 h70
  text "D" at 14383.5,-231.5 h70
  text "FILE NAME:" at 11343.5,-323.5 h45
  text ".PCB_File_Name_No_Path" at 11393.5,-443.5 h70
  text "Texas Instruments (TI) and/or its licensors do not warrant the accuracy or completeness of this specification" at 6374,-605.34 h45
  text "ENGINEER:" at 11343.5,-613.5 h45
  text "LAYOUT BY:" at 12848.5,-613.5 h45
  text "or any information contained therein. TI and/or its licensors do not warrant that this design will meet" at 6329.01,-718 h45
  text ".PRJ_Engineer" at 11393.5,-768.49 h70
  text ".PCB_Layout" at 12899,-768.49 h70
  text "the specifications, will be suitable for your application or fit for any particular purpose, or will operate in" at 6329.01,-830.67 h45
  text ".Layer_Name" at 577,-858.49 h60
  text "ALTIUM DESIGNER VERSION:" at 12848.5,-923.5 h45
  text "an implementation. TI and/or its licensors do not warrant that the design is production worthy. You should" at 6329.01,-943.33 h45
  text "completely validate and test your design implementation to confirm the system functionality for your application." at 6374,-1056 h45
  text ".print_Scale" at 11393.5,-1056.83 h70
  text ".Application_BuildNumber" at 12899,-1056.83 h70
  text "1" at 739.84,-1263.5 h70
  text "2" at 3235.5,-1263.5 h70
  text "3" at 5724.84,-1263.5 h70
  text "4" at 8231.51,-1263.5 h70
  text "5" at 10730.5,-1263.5 h70
  text "6" at 13235.5,-1263.5 h70
M10 Fab Notes:
  drawing of 185 lines, arcs and shapes, not listed
  text "DESIGN INFORMATION" at 12381.02,5910 h60
  text "MIN. TRACK WIDTH:" at 11736.46,5730 h60
  text "8" at 12832.7,5730 h60
  text "MIL" at 12987.46,5730 h60
  text "MIN. CLEARANCE:" at 11736.46,5598 h60
  text "0.2" at 12772.7,5598 h60
  text "mm" at 12987.46,5598 h60
  text "MIN. VIA PAD SIZE:" at 11736.46,5466 h60
  text "24" at 12802.71,5466 h60
  text "MIL" at 12987.46,5466 h60
  text "0.05mm (2MIL)" at 12431.46,5324.29 h60
  text "MINIMUM ANNULAR RING" at 11407.23,5320 h60
  text "EXTERNAL" at 13139.46,5320 h60
  text "PER" at 11607.23,5202 h60
  text "IPC-D-275 CLASS 2 LEVEL C" at 11827.23,5202 h60
  text "MIL, HOLES" at 13315.46,5089.71 h60
  text "+/-" at 12923,5089 h60
  text "+/-" at 13777,5089 h60
  text "REGISTRATION TOLERANCES:" at 11407.23,5084 h60
  text "METAL" at 12607,5084 h60
  text "5" at 13183.2,5084 h60
  text "3" at 14016.2,5084 h60
  text "MIL" at 14132.46,5084 h60
  text "MATERIAL:" at 11332.46,4874.54 h60
  text "FR-4 High Tg" at 12318.9,4734.21 h60
  text "FR-408" at 11753.46,4725.64 h60
  text "X" at 12165.46,4725.64 h60
  text "OTHER" at 13241.46,4725.64 h60
  text "62 MIL (1.6mm) +/-10%" at 12073.56,4562.92 h60
  text "THICKNESS:" at 11407.23,4558.64 h60
  text "X" at 11945.4,4558.64 h60
  text "OTHER" at 13358.46,4558.64 h60
  text "TOLERANCE:" at 11407.23,4400.64 h60
  text "X" at 12246.53,4400.64 h60
  text "ANSI IPC-6012 TYPE 3 CLASS 2" at 12433.48,4400.64 h60
  text "OTHER +/-" at 12433.46,4244.64 h60
  text "BOW & TWIST:" at 11407.23,4087.64 h60
  text "X" at 12246.53,4087.64 h60
  text "ANSI IPC-6012 TYPE 3 CLASS 2" at 12433.48,4087.64 h60
  text "OTHER +/-" at 12433.46,3929.13 h60
  text "DRILLING:" at 11332.46,3790.64 h60
  text "REFERENCE:" at 11407.23,3673.64 h60
  text "X" at 12055.46,3673.64 h60
  text "AS SHOWN" at 12242.46,3673.64 h60
  text "X" at 12956.46,3673.64 h60
  text "NC_DRILL FILES" at 13093.46,3673.64 h60
  text "PTH MIN COPPER THICKNESS:" at 11407.23,3515.64 h60
  text "X" at 12757.46,3515.64 h60
  text "1MIL" at 12894.46,3515.64 h60
  text "OTHER" at 13391.46,3515.64 h60
  text "BOARD FINISH:" at 11332.46,3356.64 h60
  text "SILKSCREEN:" at 11487.68,3238.64 h60
  text "X" at 12436.46,3238.64 h60
  text "TOP" at 12562.46,3238.64 h60
  text "X" at 12946.46,3238.64 h60
  text "BOTTOM" at 13073.46,3238.64 h60
  text "SILKSCREEN COLOR:" at 11487.68,3071.64 h60
  text "X" at 12435.42,3071.64 h60
  text "WHITE" at 12562.46,3071.64 h60
  text "OTHER" at 13073.46,3071.64 h60
  text "SOLDER RESIST COLOR:" at 11487.68,2901.64 h60
  text "X" at 12055.42,2742.44 h60
  text "GREEN" at 12182.46,2742.44 h60
  text "BLUE" at 12773.46,2742.44 h60
  text "OTHER" at 13311.46,2742.44 h60
  text "IMMERSION GOLD (ENIG)" at 12393.46,2553.92 h60
  text "ENEPIG" at 13731,2550.64 h60
  text "SURFACE FINISH:" at 11332.46,2549.64 h60
  text "X" at 12206.51,2549.64 h60
  text "IMM. TIN/SILVER OR EQUIV" at 11662,2392.64 h60
  text "OTHER" at 13093.46,2392.64 h60
  text "ARRAY/PANEL:" at 11332.46,2213.64 h60
  text "CUT AND TRIM PER MECH LAYER 1" at 12393.46,2209.35 h60
  text "N.C. ROUTE" at 12393.46,2057.64 h60
  text "X" at 13072.46,2057.64 h60
  text "V. SCORE" at 13259.46,2057.64 h60
  text "CERTIFICATION:" at 11332.46,1920.64 h60
  text "MATERIALS AND WORKMANSHIP FOR ALL PCBS" at 12057.46,1920.64 h60
  text "TO MEET OR EXCEED THE REQUIREMENTS OF:" at 12057.46,1822.64 h60
  text "X" at 11683.96,1686.13 h60
  text "ANSI IPC-A-600F CLASS ->" at 11822.96,1686.13 h60
  text "X" at 13462.02,1686.13 h60
  text "2" at 13580.96,1686.14 h60
  text "1" at 13265.96,1684.64 h60
  text "3" at 13934.96,1684.64 h60
  text "X" at 11686.02,1526.64 h60
  text "UL 94V-0" at 11822.96,1526.64 h60
  text "X" at 12498.02,1526.64 h60
  text "RoHS" at 12634.96,1526.64 h60
  text "OTHER" at 13279.36,1526.64 h60
  text "PER ORDER" at 13676.42,1526.64 h60
  text "ADDITIONAL REQUIREMENTS:" at 11332.46,1385.64 h60
  text "MICROSECTION:" at 11407.23,1270.64 h60
  text "YES" at 12312.96,1270.64 h60
  text "REQUIRED" at 13174.46,1114.49 h60
  text "BARE BOARD ELEC. TEST:" at 11407.23,1111.64 h60
  text "NONE" at 12712.96,1111.64 h60
  text "X" at 13047.46,1111.64 h60
  text "PER ORDER" at 13766.46,1111.64 h60
  text "MANUFACTURER'S UL:" at 11407.23,954.64 h60
  text "RAIL" at 12572.96,950.35 h60
  text "METAL" at 13064.77,950.35 h60
  text "X" at 13440,950 h60
  text "SILK" at 13576.46,950.35 h60
  text ".Layer_Name" at 577,-858.49 h60
M11 Gerber Information:
  lines w10: -292,-930.17 6308,-930.17 ; -292,-726.83 6310,-726.83 ; -292,-523.5 -292,-1133.5 3713,-1133.5 6310,-1133.5 6310,-523.5 -291.5,-523.5 -291.5,-1133.5 1284,-1133.5 ; 2173,-1133.5 2173,-523.5 ; 3440,-726.83 3440,-523.5 ; 4280,-726.83 4280,-523.5 ; 4902,-1140 4902,-937.17
  text "ALL ARTWORK VIEWED FROM TOP SIDE" at -228.5,-655.67 h60
  text "BOARD #:" at 2248,-655.67 h60
  text ".PRJ_Number" at 2793.5,-655.67 h60
  text "REV:" at 3638,-655.67 h60
  text ".PCB_Rev" at 3929.5,-655.67 h60
  text "SVN REV:" at 4476,-655.67 h60
  text ".VersionControl_RevNumber" at 4982,-655.67 h60
  text "LAYER NAME =" at -228.5,-858.49 h60
  text "TID #:" at 2248,-859 h60
  text ".TID" at 2793.5,-859 h60
  text "PLOT NAME =" at -228.5,-1064.34 h60
  text ".plot_File_Name" at 577,-1064.34 h60
  text "GENERATED    :" at 2250,-1064.34 h60
  text ".Print_Date" at 3119.5,-1064.34 h60
  text ".Print_Time" at 3848.5,-1064.34 h60
  text "TEXAS INSTRUMENTS" at 5113,-1064.34 h60
M12 Stackup:
  drawing of 191 lines, arcs and shapes, not listed
  text "Layer" at 9790.58,7830 h60
  text "Name" at 10200.49,7830 h60
  text "Material" at 11130.23,7830 h60
  text "Thickness" at 11990,7830 h60
  text "Constant" at 12639.84,7830 h60
  text "Board Layer Stack" at 13209.7,7830 h60
  text "1" at 9790.58,7710 h60
  text "Top Overlay" at 10200.49,7710 h60
  text "2" at 9790.58,7590 h60
  text "Top Solder" at 10200.49,7590 h60
  text "Solder Resist" at 11130.23,7590 h60
  text "0.40mil" at 11990,7590 h60
  text "3.5" at 12639.84,7590 h60
  text "3" at 9790.58,7470 h60
  text "Top Layer" at 10200.49,7470 h60
  text "Copper" at 11130.23,7470 h60
  text "1.40mil" at 11990,7470 h60
  text "4" at 9790.58,7350 h60
  text "Dielectric1" at 10200.49,7350 h60
  text "FR-4" at 11130.23,7350 h60
  text "59.20mil" at 11990,7350 h60
  text "4.8" at 12639.84,7350 h60
  text "5" at 9790.58,7230 h60
  text "Bottom Layer" at 10200.49,7230 h60
  text "Copper" at 11130.23,7230 h60
  text "1.40mil" at 11990,7230 h60
  text "6" at 9790.58,7110 h60
  text "Bottom Solder" at 10200.49,7110 h60
  text "Solder Resist" at 11130.23,7110 h60
  text "0.40mil" at 11990,7110 h60
  text "3.5" at 12639.84,7110 h60
  text "7" at 9790.58,6990 h60
  text "Bottom Overlay" at 10200.49,6990 h60
  text ".Layer_Name" at 577,-858.49 h60
M13 Component Bodies Top:
  text ".Layer_Name" at 577,-858.49 h60
M14 Component Bodies Bottom:
  text ".Layer_Name" at 577,-858.49 h60
M15 Courtyards Top:
  text ".Layer_Name" at 577,-858.49 h60
M16 Courtyards Bottom:
  text ".Layer_Name" at 577,-858.49 h60
Drill Drawing:
  text ".Layer_Name" at 577,-858.49 h60

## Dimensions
0,-400 to 1000,-400 on M2 Board Dimensions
